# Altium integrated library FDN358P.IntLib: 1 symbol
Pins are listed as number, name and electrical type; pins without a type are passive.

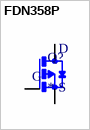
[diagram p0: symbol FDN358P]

## FDN358P
designator Q?
P-Channel 30V 1.5A (Ta) 500mW (Ta) Surface Mount SuperSOT-3; MF: ON Semiconductor; MP: FDN358P
footprint SSOT-3
pins: 1 G, 2 S, 3 D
